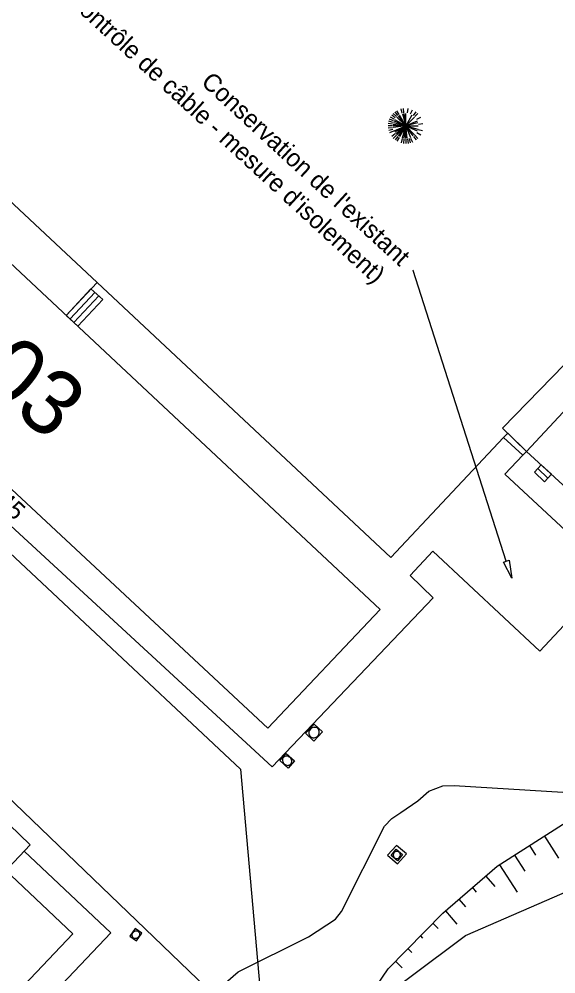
# Model space of a CAD drawing. Extents: x 343997 to 344255, y 298512 to 298767.
# Drawn here: x 344145.1 to 344175.3, y 298564.4 to 298618.2 of the extents above; entities that cross this region are included whole.
import ezdxf

# ---------------------------------------------------------------- set-up
doc = ezdxf.new("R2010")
doc.units = 0
for name, color, linetype in [('Commentaires', 7, 'Continuous'), ('Default', 7, 'Continuous'), ('DH_CADRE-CARTOUCHE-NORD', 7, 'Continuous'), ('DH_TEXTE', 7, 'Continuous'), ('GO_DALLE', 7, 'Continuous'), ('GO_ESCALIER', 7, 'Continuous'), ('O-Projet New VRD', 7, 'Continuous'), ('PC_REBAR', 7, 'Continuous'), ('PS_HATCH', 7, 'Continuous'), ('PS_OBJECT', 7, 'Continuous'), ('PS_PLATE', 7, 'Continuous'), ('RES_EAU PLUVIALE', 7, 'Continuous')]:
    doc.layers.add(name, color=color, linetype=linetype)

# ---------------------------------------------------------------- blocks, each defined once
blk = doc.blocks.new('REG_INC')
at = {"layer": 'Default'}
for p, q in [((0, 0.1), (0.1, 0.1)), ((0, 0), (0, 0.1)), ((0.1, 0.1), (0.1, 0)), ((0.1, 0), (0, 0))]:
    blk.add_line(p, q, dxfattribs=at)
for centre, start, end in [((0.0498, 0.05), 135.00554, 180.00554), ((0.05, 0.0498), 90.00577, 135.00577), ((0.05, 0.05), 45.00687, 90.00687), ((0.0499, 0.0499), 0.00663, 45.00663), ((0.0501, 0.05), 180.00663, 225.00663), ((0.0499, 0.0498), 225.00686, 270.00686), ((0.0499, 0.05), 270.00577, 315.00577), ((0.0501, 0.0499), 315.00554, 0.00554)]:
    blk.add_arc(centre, 0.044, start, end, dxfattribs=at)
blk = doc.blocks.new('ARB2')
at = {"layer": 'Default'}
for p, q in [((-0.0575, 0.0453), (-0.0775, 0.0605)), ((-0.0513, 0.0525), (-0.0688, 0.0702)), ((-0.0438, 0.0589), (-0.0588, 0.0786)), ((-0.0356, 0.0642), (-0.0481, 0.0858)), ((-0.0181, 0.0716), (-0.0244, 0.0956)), ((-0.0088, 0.0736), (-0.0119, 0.0983)), ((0.0106, 0.0736), (0.0144, 0.0983)), ((0.0287, 0.0684), (0.0388, 0.0914)), ((0.0456, 0.0589), (0.0612, 0.0786)), ((0.0531, 0.0525), (0.0706, 0.0702)), ((-0.0731, 0), (-0.0981, 0)), ((-0.0725, 0.01), (-0.0969, 0.0133)), ((-0.0706, 0.0195), (-0.0944, 0.0259)), ((-0.0675, 0.0286), (-0.09, 0.0381)), ((-0.0631, 0.0373), (-0.0844, 0.0497)), ((0.065, 0.0373), (0.0862, 0.0497)), ((0.0744, 0.01), (0.0987, 0.0133)), ((-0.0725, -0.01), (-0.0969, -0.0133)), ((-0.0706, -0.0195), (-0.0944, -0.0259)), ((-0.0675, -0.0287), (-0.09, -0.0383)), ((-0.0575, -0.0455), (-0.0775, -0.0605)), ((-0.0513, -0.0527), (-0.0688, -0.0702)), ((0.0531, -0.0527), (0.0706, -0.0702)), ((0.065, -0.0373), (0.0862, -0.0498)), ((0.0725, -0.0195), (0.0963, -0.0259)), ((-0.0438, -0.0591), (-0.0588, -0.0787)), ((-0.0356, -0.0644), (-0.0481, -0.0859)), ((-0.0181, -0.0717), (-0.0244, -0.0956)), ((-0.0088, -0.0737), (-0.0119, -0.0983)), ((0.0013, -0.0741), (0.0013, -0.0989)), ((0.0106, -0.0737), (0.0144, -0.0983)), ((0.02, -0.0717), (0.0263, -0.0956)), ((0.0287, -0.0686), (0.0388, -0.0916)), ((0.0456, -0.0591), (0.0612, -0.0787))]:
    blk.add_line(p, q, dxfattribs=at)
for points in [[(-0.0688, 0.0091), (0.0013, 0), (-0.0338, 0.0608)], [(-0.0419, 0.0556), (0.0013, 0), (-0.0638, 0.0269)], [(-0.0169, 0.0677), (0.0013, 0), (-0.06, 0.035)], [(0.0013, 0.0008), (0.0013, 0), (-0.0081, 0.0695)], [(0.0362, 0.0608), (0.0013, 0), (0.0013, 0.0702)], [(-0.0487, -0.0497), (0.0013, 0), (-0.0694, 0)], [(-0.0638, -0.0269), (0.0013, 0), (-0.0688, -0.0092)], [(-0.0487, 0.0495), (0.0013, 0), (-0.0669, 0.0181)], [(-0.0169, -0.0678), (0.0013, 0), (-0.06, -0.0352)], [(-0.0544, -0.0428), (0.0013, 0), (-0.0338, -0.0608)], [(-0.0081, -0.0695), (0.0013, 0), (-0.0419, -0.0558)], [(0.0013, -0.0702), (0.0013, 0), (0, 0)], [(0.0656, 0.0269), (0.0013, 0), (0.0506, 0.0495)], [(0.0688, 0.0181), (0.0013, 0), (0.0713, 0)], [(0.0438, -0.0558), (0.0013, 0), (0.0656, -0.0269)], [(0.0506, -0.0497), (0.0013, 0), (0.0688, -0.0181)], [(0.01, -0.0695), (0.0013, 0), (0.0281, -0.0648)], [(0.0019, 0), (0.0013, 0), (0.0013, -0.0009)]]:
    blk.add_lwpolyline(points, dxfattribs=at)

msp = doc.modelspace()

# ---------------------------------------------------------------- linework, layer by layer
at = {"layer": 'Commentaires'}
for points in [[(344167.255, 298604.053), (344167.249, 298604.059)], [(344172.505, 298587.662), (344167.255, 298604.053)]]:
    msp.add_lwpolyline(points, dxfattribs=at)
msp.add_lwpolyline([(344172.664, 298587.712), (344172.81, 298586.709), (344172.346, 298587.611)], close=True, dxfattribs=at)
at = {"layer": 'DH_CADRE-CARTOUCHE-NORD'}
msp.add_line((344099.715, 298617.296), (344158.902, 298560.479), dxfattribs=at)
msp.add_lwpolyline([(344122.446, 298608.863), (344157.538, 298575.936), (344158.902, 298560.479)], dxfattribs=at)
msp.add_lwpolyline([(344142.714, 298574.538), (344145.689, 298571.68), (344144.477, 298570.368), (344141.502, 298573.309)], close=True, dxfattribs=at)
at = {"layer": 'GO_DALLE'}
for points in [[(344173.637, 298593.851), (344172.292, 298595.161), (344185.567, 298608.8), (344198.259, 298622.397), (344163.217, 298655.561), (344163.898, 298656.291), (344171.693, 298664.218), (344209.192, 298629.258), (344201.744, 298621.299), (344205.95, 298617.379), (344203.771, 298607.721), (344197.46, 298609.156), (344192.341, 298613.899), (344190.988, 298612.393), (344196.963, 298606.8), (344195.985, 298605.701)], [(344173.444, 298593.641), (344172.427, 298592.568), (344178.462, 298586.939), (344174.396, 298582.587), (344168.376, 298588.228), (344167.085, 298586.853), (344168.386, 298585.586), (344159.324, 298576.069), (344121.411, 298611.054), (344130.716, 298620.945), (344149.461, 298603.379), (344147.717, 298601.519)], [(344149.461, 298603.379), (344166.011, 298587.87), (344172.356, 298594.641)], [(344173.444, 298593.641), (344172.356, 298594.641)], [(344179.76, 298588.225), (344178.462, 298586.939), (344172.427, 298592.568), (344173.444, 298593.641), (344173.637, 298593.851)], [(344145.36, 298571.324), (344150.236, 298566.706), (344141.289, 298557.281), (344123.303, 298574.184), (344132.335, 298583.661), (344140.996, 298575.54), (344140.93, 298575.464), (344141.582, 298574.891), (344141.725, 298575.026), (344141.55, 298575.188), (344141.782, 298575.465), (344142.714, 298574.538)]]:
    msp.add_lwpolyline(points, dxfattribs=at)
msp.add_lwpolyline([(344166.885, 298571.16), (344166.324, 298571.64), (344165.819, 298571.088), (344166.38, 298570.609)], close=True, dxfattribs=at)
at = {"layer": 'GO_ESCALIER'}
for points in [[(344172.585, 298594.876), (344172.356, 298594.641), (344173.444, 298593.641), (344173.637, 298593.851)], [(344175.045, 298592.557), (344174.66, 298592.137), (344174.086, 298592.684), (344174.462, 298593.093)]]:
    msp.add_lwpolyline(points, close=True, dxfattribs=at)
msp.add_lwpolyline([(344174.852, 298592.347), (344174.274, 298592.889)], dxfattribs=at)
at = {"layer": 'PS_HATCH'}
msp.add_lwpolyline([(344156.256, 298563.524), (344157.409, 298564.509), (344161.369, 298566.478), (344162.88, 298567.483), (344163.228, 298567.922), (344165.643, 298572.732), (344166.068, 298573.157), (344166.564, 298573.494), (344167.517, 298574.16), (344168.147, 298574.694), (344168.934, 298574.993), (344169.564, 298575.023), (344177.835, 298574.512)], dxfattribs=at)
at = {"layer": 'PS_OBJECT'}
for p, q in [((344174.649, 298572.167), (344175.444, 298570.924)), ((344173.806, 298571.627), (344174.146, 298571.096)), ((344172.964, 298571.088), (344173.545, 298570.18)), ((344172.121, 298570.549), (344173.115, 298568.997)), ((344171.352, 298569.912), (344171.866, 298569.316)), ((344170.595, 298569.258), (344170.815, 298569.004)), ((344169.838, 298568.605), (344170.214, 298568.169)), ((344169.081, 298567.951), (344169.723, 298567.207)), ((344168.368, 298567.25), (344168.668, 298566.955)), ((344167.667, 298566.537), (344167.795, 298566.411)), ((344166.965, 298565.823), (344167.184, 298565.608)), ((344166.264, 298565.11), (344166.638, 298564.742))]:
    msp.add_line(p, q, dxfattribs=at)
for points in [[(344163.934, 298561.868), (344170.201, 298566.564), (344176.522, 298569.299), (344180.879, 298572.338), (344183.313, 298574.136), (344185.048, 298576.477), (344188.051, 298580.099), (344191.638, 298583.956), (344195.571, 298587.909), (344198.338, 298590.807), (344202.379, 298595.055), (344209.468, 298599.999), (344216.32, 298605.698), (344221.544, 298609.146), (344226.03, 298610.067), (344230.196, 298608.376), (344234.376, 298605.349), (344238.337, 298601.801), (344240.148, 298600.253)], [(344163.934, 298561.868), (344165.849, 298564.688), (344168.923, 298567.814), (344171.996, 298570.469), (344176.091, 298573.09)]]:
    msp.add_lwpolyline(points, dxfattribs=at)
at = {"layer": 'PS_PLATE'}
for points in [[(344159.085, 298578.25), (344123.824, 298611.129), (344130.237, 298617.899), (344165.405, 298584.943)], [(344173.637, 298593.851), (344189.896, 298611.294), (344195.985, 298605.701), (344179.76, 298588.225)], [(344125.459, 298574.243), (344141.227, 298559.424), (344148.086, 298566.649), (344132.39, 298581.516)]]:
    msp.add_lwpolyline(points, close=True, dxfattribs=at)
at = {"layer": 'RES_EAU PLUVIALE'}
msp.add_lwpolyline([(344147.717, 298601.519), (344149.113, 298603.008), (344149.78, 298602.408), (344148.372, 298600.905)], close=True, dxfattribs=at)
for points in [[(344147.936, 298601.313), (344149.336, 298602.807)], [(344149.557, 298602.609), (344148.153, 298601.111)]]:
    msp.add_lwpolyline(points, dxfattribs=at)

# ---------------------------------------------------------------- block references
at = {"layer": 'PC_REBAR', "xscale": 10, "yscale": 10}
msp.add_blockref('ARB2', (344166.826, 298612.196), dxfattribs=at)
at = {"layer": 'RES_EAU PLUVIALE'}
for p, xscale, yscale, rotation in [((344161.685, 298578.474), 7.012818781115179, 6.40469502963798, -133.01802000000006), ((344160.582, 298576.404), 6.328322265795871, 5.48755509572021, 138.24152999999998), ((344166.307, 298571.423), 4.52665970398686, 4.6586556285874, -129.82707000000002), ((344151.974, 298566.694), 5.16732783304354, -4.48736144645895, -124.32267000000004)]:
    msp.add_blockref('REG_INC', p, dxfattribs=dict(at, xscale=xscale, yscale=yscale, rotation=rotation))

# ---------------------------------------------------------------- texts
at = {"layer": 'Commentaires'}
for s, p in [("(Contrôle de câble - mesure d'isolement)", (344147.356, 298619.58)), ("Conservation de l'existant", (344155.265, 298614.588))]:
    msp.add_text(s, height=1.00027, rotation=317.3672, dxfattribs=at).set_placement(p)
at = {"layer": 'DH_TEXTE'}
msp.add_text('0003', height=3.662, rotation=320.3665, dxfattribs=at).set_placement((344138.412, 298601.304))
at = {"layer": 'O-Projet New VRD'}
msp.add_text('3 Ø 45', height=1.0003, rotation=317.3672, dxfattribs=at).set_placement((344141.888, 298592.628))

doc.saveas('drawing.dxf')
